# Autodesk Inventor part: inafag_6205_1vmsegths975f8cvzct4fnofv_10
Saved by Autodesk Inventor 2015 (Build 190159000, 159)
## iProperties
Company: TraceParts S.A.
Created: 2012-12
Part Number: inafag_6205_1vmsegths975f8cvzct4fnofv_10
Checked By: TraceParts S.A.
Catalog Web Link: www.traceparts.com
Document SubType Name: Modeling
Designer: TraceParts
Material: Generic
Density: 1 g/cm^3
Appearance: Default
Author: TraceParts
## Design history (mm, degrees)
feature "inafag_6205_1vmsegths975f8cvzct4fnofv"
body "Solid1"
